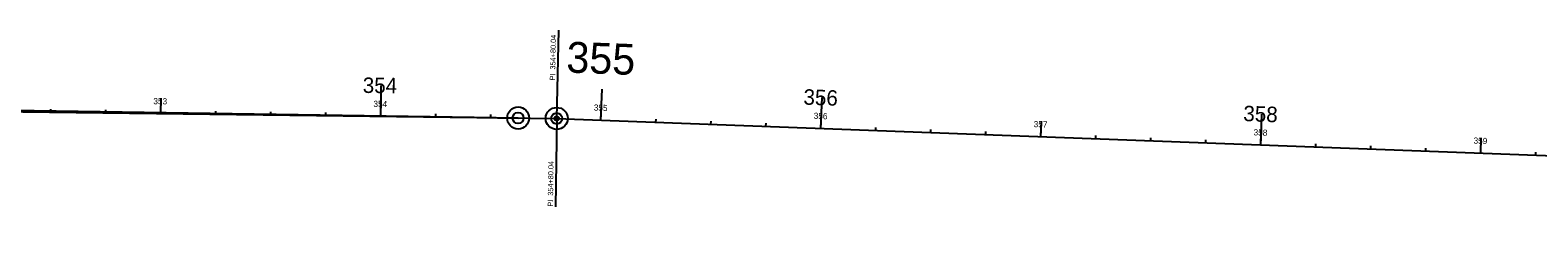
# Model space of a CAD drawing. Extents: x 250548 to 823554, y 101012 to 226545.
# Drawn here: x 594802 to 595487, y 223386 to 223476 of the extents above; entities that cross this region are included whole.
import ezdxf

# ---------------------------------------------------------------- set-up
doc = ezdxf.new("R2010")
doc.units = 0
for name, color, linetype in [('E_DTM_Boundary', 7, 'Continuous'), ('E_DTM_BreakLines', 7, 'Continuous'), ('E_DTM_CompDiscontinuity', 7, 'Continuous'), ('E_DTM_ObscureArea', 7, 'Continuous'), ('E_DTM_RidgeLines', 7, 'Continuous'), ('E_DTM_SlopeTop', 7, 'Continuous'), ('E_DTM_WeakAreaApprox', 7, 'Continuous'), ('E_MAP_ContoursAnnot', 7, 'Continuous'), ('E_MAP_ContoursIndex', 7, 'Continuous'), ('E_MAP_ContoursInter', 7, 'Continuous'), ('E_MAP_ContoursInterWk', 7, 'Continuous'), ('E_MAP_Control', 7, 'Continuous'), ('E_MAP_GridLines', 7, 'Continuous'), ('E_MAP_PhotoCenter', 7, 'Continuous'), ('E_MAP_SpotElev', 7, 'Continuous'), ('P_MISC', 7, 'Continuous'), ('P_RDWY_LaneEdge', 7, 'Continuous'), ('P_RDWY_PavtEdge', 7, 'Continuous'), ('P_RDWY_ShldPaved', 7, 'Continuous')]:
    doc.layers.add(name, color=color, linetype=linetype)

msp = doc.modelspace()

# ---------------------------------------------------------------- linework, layer by layer
at = {"layer": 'E_DTM_Boundary'}
for p, q in [((594458.12, 223443.61), (595041.7, 223436.37)), ((595041.7, 223436.37), (596401.17, 223385.5))]:
    msp.add_line(p, q, dxfattribs=at)
at = {"layer": 'E_DTM_BreakLines'}
msp.add_lwpolyline([(595041.7, 223436.37), (595041.2, 223396.38)], dxfattribs=at)
at = {"layer": 'E_DTM_CompDiscontinuity'}
msp.add_circle((595041.7, 223436.37), 1, dxfattribs=at)
at = {"layer": 'E_DTM_ObscureArea'}
for points in [[(594961.84, 223451.36), (594961.66, 223437.37)], [(595162.1, 223445.88), (595161.57, 223431.89)], [(594996.17, 223437.01), (595024.17, 223436.59)], [(594996.17, 223437.01), (595024.17, 223436.59)], [(595010.17, 223436.8), (595024.17, 223436.59)], [(595010.17, 223436.8), (595024.17, 223436.59)], [(595361.96, 223438.4), (595361.43, 223424.41)]]:
    msp.add_lwpolyline(points, dxfattribs=at)
at = {"layer": 'E_DTM_RidgeLines'}
msp.add_lwpolyline([(595041.7, 223436.37), (595042.7, 223476.36)], dxfattribs=at)
at = {"layer": 'E_DTM_SlopeTop'}
msp.add_lwpolyline([(595024.17, 223436.59), (594624.21, 223442.54)], dxfattribs=at)
msp.add_lwpolyline([(595024.17, 223436.59), (594624.21, 223442.54)], dxfattribs=at)
at = {"layer": 'E_DTM_WeakAreaApprox'}
for p, q in [((594458.12, 223443.61), (595041.7, 223436.37)), ((595041.7, 223436.37), (596401.17, 223385.5))]:
    msp.add_line(p, q, dxfattribs=at)
at = {"layer": 'E_MAP_ContoursAnnot'}
for centre in [(595024.17, 223436.59), (595024.17, 223436.59), (595041.7, 223436.37)]:
    msp.add_circle(centre, 5, dxfattribs=at)
at = {"layer": 'E_MAP_ContoursIndex'}
for p, q in [((594457.8, 223443.62), (595041.7, 223436.37)), ((595041.7, 223436.37), (596401.17, 223385.5))]:
    msp.add_line(p, q, dxfattribs=at)
at = {"layer": 'E_MAP_ContoursInterWk'}
msp.add_lwpolyline([(595024.17, 223436.59), (594824.19, 223439.56)], dxfattribs=at)
msp.add_lwpolyline([(595024.17, 223436.59), (594824.19, 223439.56)], dxfattribs=at)
at = {"layer": 'E_MAP_Control'}
for points in [[(594961.75, 223444.37), (594961.66, 223437.37)], [(594861.71, 223442.11), (594861.67, 223438.61)], [(595061.77, 223439.12), (595061.64, 223435.63)], [(595161.84, 223438.88), (595161.57, 223431.89)], [(595261.63, 223431.65), (595261.5, 223428.15)], [(595361.7, 223431.4), (595361.43, 223424.41)], [(595461.49, 223424.17), (595461.36, 223420.67)]]:
    msp.add_lwpolyline(points, dxfattribs=at)
at = {"layer": 'E_MAP_PhotoCenter'}
for centre in [(595024.17, 223436.59), (595024.17, 223436.59), (595041.7, 223436.37)]:
    msp.add_circle(centre, 2.5, dxfattribs=at)
at = {"layer": 'E_MAP_SpotElev'}
for points in [[(594811.69, 223440.63), (594811.67, 223439.23)], [(594836.69, 223440.32), (594836.67, 223438.92)], [(594861.71, 223441.41), (594861.67, 223438.61)], [(594886.69, 223439.7), (594886.67, 223438.3)], [(594911.68, 223439.39), (594911.67, 223437.99)], [(594936.68, 223439.08), (594936.67, 223437.68)], [(594961.7, 223440.17), (594961.66, 223437.37)], [(594986.68, 223438.46), (594986.66, 223437.06)], [(595011.68, 223438.15), (595011.66, 223436.75)], [(595036.67, 223437.84), (595036.66, 223436.44)], [(595061.75, 223438.42), (595061.64, 223435.63)], [(595086.68, 223436.09), (595086.63, 223434.69)], [(595111.66, 223435.16), (595111.61, 223433.76)], [(595136.64, 223434.22), (595136.59, 223432.82)], [(595161.68, 223434.69), (595161.57, 223431.89)], [(595186.61, 223432.35), (595186.56, 223430.95)], [(595211.59, 223431.42), (595211.54, 223430.02)], [(595236.57, 223430.48), (595236.52, 223429.08)], [(595261.61, 223430.95), (595261.5, 223428.15)], [(595286.54, 223428.61), (595286.49, 223427.21)], [(595311.52, 223427.68), (595311.47, 223426.28)], [(595336.5, 223426.74), (595336.45, 223425.34)], [(595361.54, 223427.21), (595361.43, 223424.41)], [(595386.47, 223424.87), (595386.42, 223423.47)], [(595411.45, 223423.94), (595411.4, 223422.54)], [(595436.43, 223423), (595436.38, 223421.6)], [(595461.47, 223423.47), (595461.36, 223420.67)], [(595486.4, 223421.13), (595486.35, 223419.73)]]:
    msp.add_lwpolyline(points, dxfattribs=at)
at = {"layer": 'P_RDWY_LaneEdge'}
for p, q in [((594457.8, 223443.62), (595041.7, 223436.37)), ((595041.7, 223436.37), (596401.17, 223385.5))]:
    msp.add_line(p, q, dxfattribs=at)
at = {"layer": 'P_RDWY_PavtEdge'}
msp.add_lwpolyline([(595024.17, 223436.59), (594924.18, 223438.08)], dxfattribs=at)
msp.add_lwpolyline([(595024.17, 223436.59), (594924.18, 223438.08)], dxfattribs=at)
at = {"layer": 'P_RDWY_ShldPaved'}
for points in [[(595062.17, 223449.62), (595061.64, 223435.63)], [(594861.76, 223445.61), (594861.67, 223438.61)], [(594961.75, 223444.37), (594961.66, 223437.37)], [(595161.84, 223438.88), (595161.57, 223431.89)], [(595261.77, 223435.14), (595261.5, 223428.15)], [(595361.7, 223431.4), (595361.43, 223424.41)], [(595461.63, 223427.66), (595461.36, 223420.67)]]:
    msp.add_lwpolyline(points, dxfattribs=at)

# ---------------------------------------------------------------- texts
at = {"layer": 'E_DTM_BreakLines'}
msp.add_text('PI  354+80.04', height=2.4, rotation=89.28921, dxfattribs=at).set_placement((595040, 223396.39))
at = {"layer": 'E_DTM_RidgeLines'}
msp.add_text('PI  354+80.04', height=2.4, rotation=88.57312, dxfattribs=at).set_placement((595040.93, 223453.57))
at = {"layer": 'E_MAP_ContoursInter'}
msp.add_text('355', height=14, rotation=357.85703, dxfattribs=at).set_placement((595045.91, 223457.23))
at = {"layer": 'E_MAP_GridLines'}
for s, rotation, p in [('353', 359.28921, (594858.42, 223442.85)), ('354', 359.28921, (594958.41, 223441.61)), ('355', 357.85703, (595058.5, 223439.95)), ('356', 357.85703, (595158.43, 223436.21)), ('357', 357.85703, (595258.36, 223432.47)), ('358', 357.85703, (595358.29, 223428.73)), ('359', 357.85703, (595458.22, 223424.99))]:
    msp.add_text(s, height=2.8, rotation=rotation, dxfattribs=at).set_placement(p)
at = {"layer": 'P_MISC'}
for s, rotation, p in [('354', 359.28912, (594953.53, 223447.97)), ('356', 357.85703, (595153.7, 223442.69)), ('358', 357.85703, (595353.56, 223435.21))]:
    msp.add_text(s, height=7, rotation=rotation, dxfattribs=at).set_placement(p)

doc.saveas('drawing.dxf')
